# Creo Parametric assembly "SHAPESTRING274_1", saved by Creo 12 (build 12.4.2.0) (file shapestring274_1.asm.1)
Units: Custom; MM, KILOGRAM, SECS

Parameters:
  PTC_WM_ITERATION = "0"
  PTC_WM_VERSION = "-.0"
  PTC_WM_LIFECYCLE_STATE = "In Work"
  PTC_WM_LIFECYCLE = "MO_CADDocument"
  PTC_WM_CREATED_BY = "Maximilian Roepper (Z0017RMS: MO)"
  PTC_WM_CREATED_ON = "18-Sep-26 11:36:42 AM"
  PTC_WM_MODIFIED_BY = "Maximilian Roepper (Z0017RMS: MO)"
  PTC_WM_MODIFIED_ON = "18-Sep-26 11:36:46 AM"
  PDMLINKNUMBER = "PDM000071455271"
  PTC_WM_NUMBER = "PDM000071455271"

Other parameters: WEIGHT, WEIGHT_FACTOR, WEIGHT_ADD, MC_ERRORS, SUPPLIER

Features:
  1. coordinate system
  2. imported feature
  3. component "SHAPESTRING064_1"
  4. component "SHAPESTRING272_1"
  5. component "SHAPESTRING273_1"

Other named items: DRW_VIEW_ORG, ROUGH-GROB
